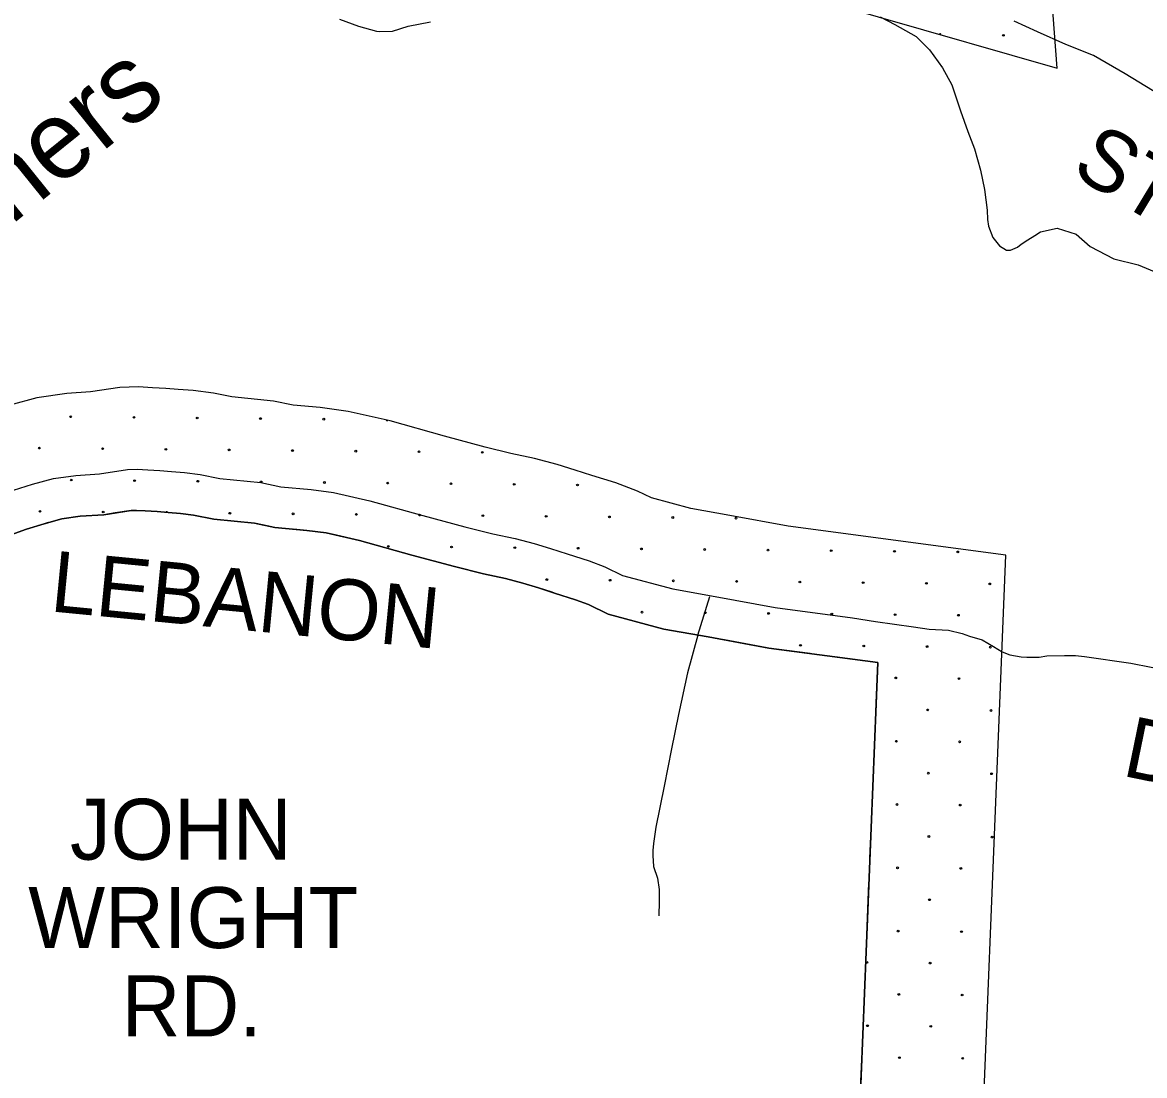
# Model space of a CAD drawing. Extents: x 1788175 to 1969470, y 584502 to 738744.
# Drawn here: x 1806805 to 1813624, y 674841 to 681239 of the extents above; entities that cross this region are included whole.
import ezdxf

# ---------------------------------------------------------------- set-up
doc = ezdxf.new("R2010")
doc.units = 0
for name, color, linetype in [('DESIGN - DRAINAGE - Bridges and Cross Drains Size Text', 7, 'Continuous'), ('DESIGN - EROSION CONTROL - Devices', 7, 'Continuous'), ('DESIGN - ROW - Right-of-Way and Easement Labels', 7, 'Continuous'), ('DESIGN - SCRATCH - User 1', 7, 'Continuous'), ('DESIGN - TRANSPORTATION - Text', 7, 'Continuous'), ('SURVEY - CONTOURS - Index with Text', 7, 'Continuous'), ('SURVEY - CONTOURS - Intermediate with optional Text', 7, 'Continuous'), ('SURVEY - DRAINAGE - Area Shapes', 7, 'Continuous'), ('SURVEY - TRANSPORTATION - Roads', 7, 'Continuous'), ('SURVEY - VEGETATION - Features with Text', 7, 'Continuous')]:
    doc.layers.add(name, color=color, linetype=linetype)

msp = doc.modelspace()

# ---------------------------------------------------------------- linework, layer by layer
at = {"layer": 'DESIGN - EROSION CONTROL - Devices'}
for centre in [(1812766.5, 681160.6), (1807098.1, 678843.6), (1807482.7, 678839.9), (1807867.2, 678836.2), (1808251.8, 678832.4), (1808636.3, 678828.7), (1806907.7, 678653.2), (1807292.2, 678649.5), (1807676.8, 678645.7), (1808061.4, 678642), (1808445.9, 678638.3), (1808830.5, 678634.5), (1809215, 678630.8), (1809599.6, 678627.1), (1807101.8, 678459.1), (1807486.4, 678455.3), (1807870.9, 678451.6), (1808255.5, 678447.9), (1808640, 678444.1), (1809024.6, 678440.4), (1809409.2, 678436.7), (1809793.7, 678432.9), (1810178.3, 678429.2), (1806911.4, 678268.7), (1807296, 678264.9), (1808065.1, 678257.5), (1808449.6, 678253.7), (1808834.2, 678250), (1809218.7, 678246.3), (1809603.3, 678242.5), (1809987.8, 678238.8), (1810372.4, 678235.1), (1810757, 678231.3), (1811141.5, 678227.6), (1809028.3, 678055.8), (1809412.9, 678052.1), (1809797.4, 678048.4), (1810182, 678044.6), (1810566.5, 678040.9), (1810951.1, 678037.2), (1811335.7, 678033.4), (1811720.2, 678029.7), (1812104.8, 678026), (1812489.3, 678022.2), (1809991.6, 677854.2), (1810376.1, 677850.5), (1810760.7, 677846.8), (1811145.2, 677843), (1811529.8, 677839.3), (1811914.3, 677835.6), (1812298.9, 677831.8), (1812683.5, 677828.1), (1810570.3, 677656.4), (1810954.8, 677652.6), (1811339.4, 677648.9), (1811723.9, 677645.2), (1812108.5, 677641.4), (1812493, 677637.7), (1811533.5, 677454.8), (1811918.1, 677451), (1812302.6, 677447.3), (1812687.2, 677443.6), (1812112.2, 677256.9), (1812496.8, 677253.1), (1812306.4, 677062.7), (1812690.9, 677059), (1812116, 676872.3), (1812500.5, 676868.6), (1812310.1, 676678.2), (1812694.7, 676674.4), (1812119.7, 676487.8), (1812504.2, 676484), (1812313.8, 676293.6), (1812698.4, 676289.9), (1812123.4, 676103.2), (1812508, 676099.5), (1812317.6, 675909.1), (1812127.2, 675718.7), (1812511.7, 675714.9), (1811936.7, 675528.3), (1812321.3, 675524.5), (1812130.9, 675334.1), (1812515.4, 675330.4), (1811940.5, 675143.7), (1812325, 675140), (1812134.6, 674949.6), (1812519.2, 674945.8)]:
    msp.add_circle(centre, 5.28, dxfattribs=at)
for centre, start, end in [((1812382, 681164.3), 359.95538, 147.8923), ((1809020.9, 678825), 195.91099, 318.36002), ((1807680.5, 678261.2), 8.20737, 161.86539)]:
    msp.add_arc(centre, 5.28, start, end, dxfattribs=at)
at = {"layer": 'DESIGN - SCRATCH - User 1'}
msp.add_line((1813094, 680960.6), (1812646.6, 686622.7), dxfattribs=at)
for points in [[(1808321.3, 681810.2), (1808942.5, 681822.8), (1809605, 681787), (1810231.2, 681730.5), (1810371.3, 681714.5), (1810417, 681707.2), (1810609.5, 681666.5), (1810870.3, 681602.1), (1810916.6, 681588.1), (1813094, 680960.6)], [(1812780.5, 678003.3), (1811457.5, 678179.3), (1811104.9, 678243.6), (1810866.9, 678286.3), (1810627.9, 678350.1), (1810542.8, 678391.8), (1810411.7, 678441.1), (1810266.1, 678486.9), (1810163.3, 678519.9), (1810053.7, 678552.9), (1809916.5, 678590.9), (1809774, 678620.4), (1809617.9, 678659.2), (1809369.4, 678725.5), (1809039, 678818.2), (1808784.8, 678876.3), (1808615, 678898.9), (1808450.6, 678913.4), (1808330.9, 678939.1), (1808077.9, 678963.6), (1807965.7, 678986.2), (1807841.4, 679002.2), (1807751.1, 679009.1), (1807676, 679015.6), (1807596.2, 679020), (1807510.5, 679025.5), (1807397, 679021.8), (1807218.1, 678994.7), (1807075.5, 678985), (1806891.5, 678958.2), (1806728.1, 678914.3)], [(1806711.9, 678118.6), (1806829.8, 678160.7), (1806936, 678193.6), (1807043.3, 678222.4), (1807155.3, 678238.7), (1807300, 678248.5), (1807465.5, 678273.6), (1807498.7, 678274.7), (1807551.7, 678271.3), (1807622.8, 678267.4), (1807690.2, 678261.6), (1807765, 678255.9), (1807843.7, 678245.7), (1807967.5, 678220.8), (1808215.7, 678196.7), (1808338.8, 678170.4), (1808532.4, 678153.3), (1808651.4, 678137.4), (1808854, 678091.1), (1809171.4, 678002.1), (1809430.8, 677932.9), (1809607.6, 677889), (1809740.2, 677861.5), (1809845.4, 677832.4), (1809940.5, 677803.8), (1810038.9, 677772.1), (1810166.9, 677731.9), (1810245.2, 677702.4), (1810363.8, 677644.4), (1810703.6, 677553.6), (1810971.3, 677505.6), (1811340.6, 677438.2), (1812003.6, 677350)], [(1809506.7, 673864.3), (1810689.3, 673592.4), (1812584.5, 673149.6), (1812780.5, 678003.3)], [(1812003.6, 677350), (1811871.8, 674086.3), (1810858.6, 674323), (1808868.8, 674780.5)]]:
    msp.add_lwpolyline(points, dxfattribs=at)
at = {"layer": 'DESIGN - TRANSPORTATION - Text'}
for points in [[(1808732.5, 681258.9), (1808846.4, 681216.8), (1808956.3, 681186.7), (1808974.3, 681184.7), (1809054.2, 681186.6), (1809148.2, 681216.4), (1809284.2, 681242.3)], [(1812017.1, 681273), (1812107, 681227), (1812236.8, 681152.9), (1812316.7, 681072.9), (1812396.4, 680962.9), (1812452.2, 680860.9), (1812506, 680703), (1812549.7, 680577.1), (1812591.6, 680471.1), (1812627.3, 680341.2), (1812651.1, 680223.3), (1812666.9, 680099.4), (1812670.8, 680041.4), (1812676.8, 680001.5), (1812702.6, 679933.5), (1812742.5, 679881.5), (1812784.5, 679855.5), (1812810.5, 679855.5), (1812852.5, 679873.4), (1812874.5, 679891.4), (1812914.5, 679919.3), (1812956.6, 679945.2), (1812992.6, 679967.1), (1813092.6, 679989), (1813208.5, 679952.9), (1813294.3, 679878.9), (1813438.1, 679802.8), (1813586, 679766.6), (1813789.8, 679682.5)]]:
    msp.add_lwpolyline(points, dxfattribs=at)
at = {"layer": 'SURVEY - CONTOURS - Index with Text'}
msp.add_lwpolyline([(1815226.2, 679882.8), (1815129.2, 679931.4), (1814875.6, 680081.6), (1814610, 680239.7), (1814506.2, 680295.8), (1814342.4, 680389.9), (1814246.6, 680455.9), (1814098.8, 680538), (1813885.2, 680694.1), (1813769.4, 680764.2), (1813673.5, 680826.3), (1813505.8, 680926.4), (1813314.1, 681038.5), (1813146.3, 681104.6), (1812974.5, 681182.8), (1812832.7, 681246.9)], dxfattribs=at)
at = {"layer": 'SURVEY - CONTOURS - Intermediate with optional Text'}
for points in [[(1806750.7, 678398), (1806866.7, 678433.8), (1806992.7, 678467.6), (1807128.7, 678487.4), (1807272.7, 678497.3), (1807442.6, 678523), (1807502.6, 678525), (1807566.6, 678520.9), (1807640.5, 678516.8), (1807710.5, 678510.7), (1807790.4, 678504.6), (1807884.4, 678492.6), (1808004.3, 678468.4), (1808254.1, 678444.2), (1808376.1, 678418), (1808559.9, 678401.8), (1808695.9, 678383.7), (1808915.7, 678333.5), (1809237.4, 678243.2), (1809493.2, 678175), (1809663, 678132.8), (1809798.9, 678104.7), (1809914.8, 678072.6), (1810014.7, 678042.5), (1810114.6, 678010.4), (1810248.5, 677968.3), (1810344.4, 677932.2), (1810451.8, 677879.6), (1810758, 677797.9), (1811015.8, 677751.6), (1811379.6, 677685.2), (1811849.3, 677622.7), (1811989.2, 677600.6), (1812220.9, 677567.9), (1812315, 677552.3), (1812432.9, 677546.1), (1812516.8, 677526.1), (1812561.3, 677511), (1812637.2, 677488), (1812706.6, 677447.9), (1812758.5, 677415.9), (1812806.5, 677397.8), (1812874.4, 677385.8), (1812908.4, 677383.7), (1812984.4, 677383.6), (1813030.4, 677391.6), (1813137.3, 677393.6), (1813204.3, 677393.4), (1813260.3, 677387.3), (1813541.8, 677345.8)], [(1813541.8, 677345.8), (1813664.4, 677322.6), (1813827.9, 677292.7), (1813991.8, 677260.6), (1814177.6, 677222.4), (1814385.5, 677192.2), (1814653.3, 677139.9), (1814965.1, 677079.6), (1815090.7, 677059.8), (1815272.8, 677025.3), (1815318.4, 677012), (1815438.9, 676985.2), (1815693.5, 676932.7)]]:
    msp.add_lwpolyline(points, dxfattribs=at)
at = {"layer": 'SURVEY - DRAINAGE - Area Shapes'}
msp.add_lwpolyline([(1810909.5, 677516.7), (1810981.8, 677752.3)], dxfattribs=at)
at = {"layer": 'SURVEY - TRANSPORTATION - Roads'}
msp.add_lwpolyline([(1810909.5, 677516.7), (1810846.9, 677287), (1810792.5, 677035.3), (1810750.1, 676825.6), (1810705.7, 676599.8), (1810653.3, 676350.1), (1810639.1, 676250.2), (1810635, 676208.2), (1810635, 676178.3), (1810640.8, 676110.3), (1810664.7, 676040.4), (1810674.6, 675970.4), (1810674.4, 675898.5), (1810672.3, 675810.6)], dxfattribs=at)
at = {"layer": 'SURVEY - VEGETATION - Features with Text'}
for points in [[(1812003.6, 677350), (1811340.6, 677438.2), (1810971.3, 677505.6), (1810703.6, 677553.6), (1810363.8, 677644.4), (1810245.2, 677702.4), (1810166.9, 677731.9), (1810038.9, 677772.1), (1809940.5, 677803.8), (1809845.4, 677832.4), (1809740.2, 677861.5), (1809607.6, 677889), (1809430.8, 677932.9), (1809171.4, 678002.1), (1808854, 678091.1), (1808651.4, 678137.4), (1808532.4, 678153.3), (1808338.8, 678170.4), (1808215.7, 678196.7), (1807967.5, 678220.8), (1807843.7, 678245.7), (1807765, 678255.9), (1807690.2, 678261.6), (1807622.8, 678267.4), (1807551.7, 678271.3), (1807498.7, 678274.7), (1807465.5, 678273.6), (1807300, 678248.5), (1807155.3, 678238.7), (1807043.3, 678222.4), (1806936, 678193.6), (1806829.8, 678160.7), (1806711.9, 678118.6)], [(1807369.2, 678259.1), (1807300, 678248.5), (1807155.3, 678238.7), (1807106.9, 678231.6)], [(1807631.9, 678266.6), (1807622.8, 678267.4), (1807551.7, 678271.3), (1807498.7, 678274.7), (1807465.5, 678273.6), (1807369.2, 678259.1)], [(1808041.9, 678213.6), (1807967.5, 678220.8), (1807843.7, 678245.7), (1807781.3, 678253.8)], [(1808303.1, 678178), (1808215.7, 678196.7), (1808041.9, 678213.6)], [(1806960.5, 678200.1), (1806936, 678193.6), (1806829.8, 678160.7), (1806711.9, 678118.6), (1806709.8, 678117.7)], [(1808712.9, 678123.4), (1808651.4, 678137.4), (1808532.4, 678153.3), (1808451.9, 678160.4)], [(1808968.9, 678058.9), (1808854, 678091.1), (1808712.9, 678123.4)], [(1809368.2, 677949.6), (1809171.4, 678002.1), (1809113.3, 678018.4)], [(1809624.3, 677885.5), (1809607.6, 677889), (1809430.8, 677932.9), (1809368.2, 677949.6)], [(1810023.4, 677777.1), (1809940.5, 677803.8), (1809845.4, 677832.4), (1809770.7, 677853.1)], [(1810272.1, 677689.3), (1810245.2, 677702.4), (1810166.9, 677731.9), (1810038.9, 677772.1), (1810023.4, 677777.1)], [(1810665.1, 677563.9), (1810410.1, 677632)], [(1810924.3, 677514), (1810703.6, 677553.6), (1810665.1, 677563.9)], [(1811331.6, 677439.9), (1811071.8, 677487.3)], [(1811593.2, 677404.6), (1811340.6, 677438.2), (1811331.6, 677439.9)], [(1808868.8, 674780.5), (1809532, 674622.3), (1810858.6, 674323), (1811871.8, 674086.3), (1812003.6, 677350)], [(1812003.6, 677350), (1811741.9, 677384.8)], [(1811993.6, 677103.7), (1812003.6, 677350)], [(1811983, 676839.9), (1811993.6, 677103.7)], [(1811966.3, 676426.3), (1811976.9, 676690)], [(1811955.6, 676162.5), (1811966.3, 676426.3)], [(1811938.9, 675748.8), (1811949.5, 676012.6)], [(1811928.2, 675485), (1811938.9, 675748.8)], [(1811911.5, 675071.4), (1811922.2, 675335.2)], [(1811900.9, 674807.6), (1811911.5, 675071.4)]]:
    msp.add_lwpolyline(points, dxfattribs=at)

# ---------------------------------------------------------------- texts
at = {"layer": 'DESIGN - DRAINAGE - Bridges and Cross Drains Size Text'}
msp.add_text('Stoners', height=475, rotation=38.8339, dxfattribs=at).set_placement((1805990.5, 679404.9))
at = {"layer": 'DESIGN - ROW - Right-of-Way and Easement Labels'}
for s, rotation, p in [('ST.', 328.82694, (1813168.3, 680324.9)), ('LEBANON', 354.45066, (1806966.6, 677662)), ('DIRT', 348.39297, (1813479.8, 676664.4))]:
    msp.add_text(s, height=370, rotation=rotation, dxfattribs=at).set_placement(p)
for s, p in [('JOHN', (1807093.8, 676152.5)), ('WRIGHT', (1806840.2, 675615.7)), ('RD.', (1807407.5, 675078.9))]:
    msp.add_text(s, height=370, dxfattribs=at).set_placement(p)

doc.saveas('drawing.dxf')
